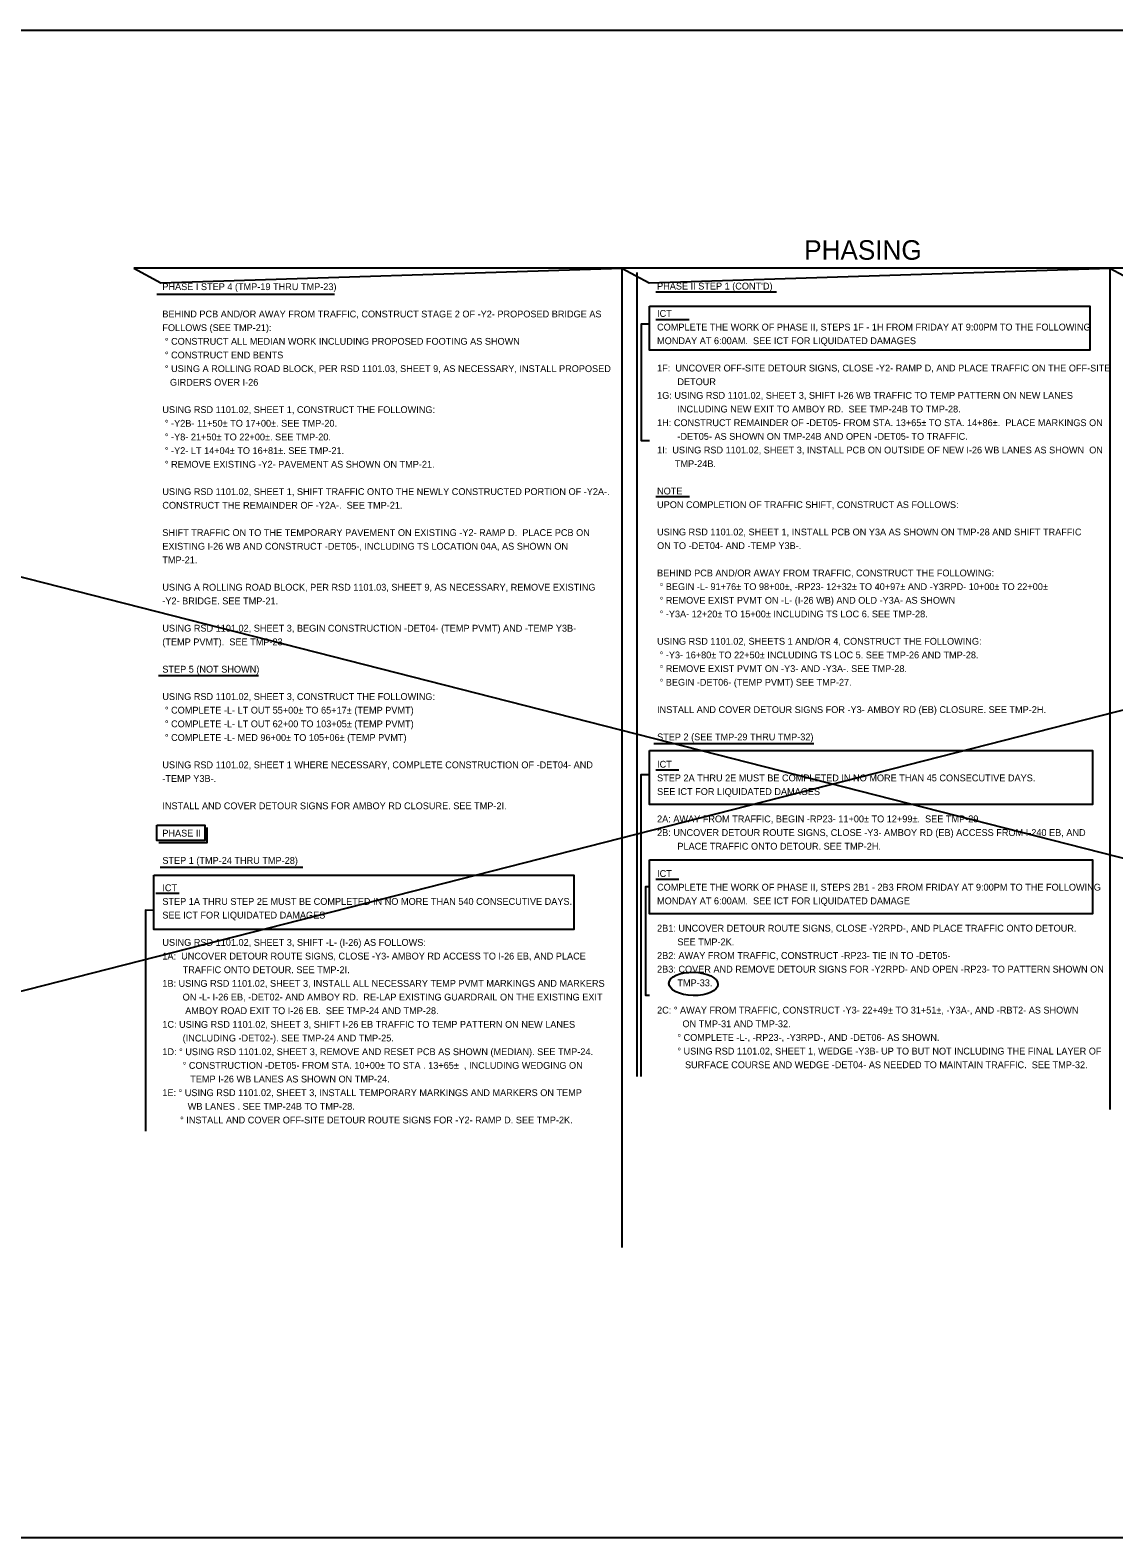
# Model space of a CAD drawing. Extents: x 2483905 to 2494512, y 366160 to 372330.
# Drawn here: x 2488905 to 2490016, y 368441 to 369986 of the extents above; entities that cross this region are included whole.
import ezdxf

# ---------------------------------------------------------------- set-up
doc = ezdxf.new("R2010")
doc.units = 0
for name, color, linetype in [('Scratch_Level_4', 7, 'Continuous'), ('Scratch_Level_6', 7, 'Continuous'), ('TC SHEET BORDER LINE THIN', 7, 'Continuous'), ('TC SHEET TEXT', 7, 'Continuous')]:
    doc.layers.add(name, color=color, linetype=linetype)

msp = doc.modelspace()

# ---------------------------------------------------------------- linework, layer by layer
at = {"layer": 'Scratch_Level_4'}
for p, q in [((2486701.2, 368441.1), (2492754.6, 369986.2)), ((2486701.2, 369986.2), (2492754.6, 368441.1))]:
    msp.add_line(p, q, dxfattribs=at)
msp.add_lwpolyline([(2486701.2, 369986.2), (2492754.6, 369986.2), (2492754.6, 368441.1), (2486701.2, 368441.1)], close=True, dxfattribs=at)
msp.add_ellipse((2489584.9, 369008.8), major_axis=(25.1, -0.5), ratio=0.476489, dxfattribs=at)
at = {"layer": 'Scratch_Level_6'}
msp.add_lwpolyline([(2489011.6, 369742.3), (2489039.5, 369727.3), (2489511.6, 369742.3), (2489539.5, 369727.3), (2490011.6, 369742.3), (2490039.5, 369727.3)], dxfattribs=at)
at = {"layer": 'TC SHEET BORDER LINE THIN'}
for p, q in [((2490511.6, 369742.3), (2489011.6, 369742.3)), ((2489511.6, 369742.3), (2489511.6, 368738.5)), ((2490011.6, 369742.3), (2490011.6, 368880.2)), ((2489035.4, 369715.6), (2489217.2, 369715.6)), ((2489546.4, 369718), (2489670.1, 369718)), ((2489546.4, 369689.8), (2489580.5, 369689.8)), ((2489546.4, 369508.2), (2489580.8, 369508.2)), ((2489036.9, 369324.9), (2489139.3, 369324.9)), ((2489544.5, 369255), (2489708.3, 369255)), ((2489546.4, 369228.2), (2489569.9, 369228.2)), ((2489038.6, 369128.3), (2489184.8, 369128.3)), ((2489546.4, 369116.2), (2489569.9, 369116.2)), ((2489034.4, 369101.9), (2489058, 369101.9))]:
    msp.add_line(p, q, dxfattribs=at)
for points in [[(2489526.8, 369738), (2489526.8, 368913.9)], [(2489540.1, 369685), (2489531.5, 369685), (2489531.5, 369565.6), (2489540.1, 369565.6)], [(2489540.1, 369223.1), (2489531.2, 369223.1), (2489531.2, 368913.9)], [(2489086.4, 369169.1), (2489086.4, 369153.4), (2489037.4, 369153.4)], [(2489540.1, 369108.3), (2489535.7, 369108.3), (2489535.7, 368997.4), (2489540.1, 368997.4)], [(2489031.5, 369084.1), (2489023.5, 369084.2), (2489023.5, 368857.8)]]:
    msp.add_lwpolyline(points, dxfattribs=at)
for points in [[(2489540.1, 369703.2), (2489990.9, 369703.2), (2489990.9, 369658.4), (2489540.1, 369658.4)], [(2489540.1, 369248.1), (2489993.8, 369248.1), (2489993.8, 369192.5), (2489540.1, 369192.5)], [(2489035.4, 369171.5), (2489084.4, 369171.5), (2489084.4, 369155.8), (2489035.4, 369155.8)], [(2489540.1, 369136.1), (2489993.8, 369136.1), (2489993.8, 369080.5), (2489540.1, 369080.5)], [(2489032.2, 369120.1), (2489462.4, 369120.1), (2489462.4, 369064.5), (2489032.2, 369064.5)]]:
    msp.add_lwpolyline(points, close=True, dxfattribs=at)

# ---------------------------------------------------------------- texts
for s, p in [('PHASE I STEP 4 (TMP-19 THRU TMP-23)', (2489040.9, 369719.8)), ("PHASE II STEP 1 (CONT'D)", (2489547.7, 369720.4)), ('BEHIND PCB AND/OR AWAY FROM TRAFFIC, CONSTRUCT STAGE 2 OF -Y2- PROPOSED BRIDGE AS', (2489040.9, 369691.8)), ('ICT', (2489547.7, 369692.4)), ('FOLLOWS (SEE TMP-21):', (2489040.9, 369677.8)), ('COMPLETE THE WORK OF PHASE II, STEPS 1F - 1H FROM FRIDAY AT 9:00PM TO THE FOLLOWING', (2489547.7, 369678.4)), (' ° CONSTRUCT ALL MEDIAN WORK INCLUDING PROPOSED FOOTING AS SHOWN', (2489040.9, 369663.8)), ('MONDAY AT 6:00AM.  SEE ICT FOR LIQUIDATED DAMAGES', (2489547.7, 369664.4)), (' ° CONSTRUCT END BENTS', (2489040.9, 369649.8)), (' ° USING A ROLLING ROAD BLOCK, PER RSD 1101.03, SHEET 9, AS NECESSARY, INSTALL PROPOSED ', (2489040.9, 369635.8)), ('1F:  UNCOVER OFF-SITE DETOUR SIGNS, CLOSE -Y2- RAMP D, AND PLACE TRAFFIC ON THE OFF-SITE ', (2489547.7, 369636.4)), ('   GIRDERS OVER I-26', (2489040.9, 369621.8)), ('        DETOUR', (2489547.7, 369622.4)), ('1G: USING RSD 1101.02, SHEET 3, SHIFT I-26 WB TRAFFIC TO TEMP PATTERN ON NEW LANES', (2489547.7, 369608.4)), ('USING RSD 1101.02, SHEET 1, CONSTRUCT THE FOLLOWING:', (2489040.9, 369593.8)), ('        INCLUDING NEW EXIT TO AMBOY RD.  SEE TMP-24B TO TMP-28.', (2489547.7, 369594.4)), (' ° -Y2B- 11+50± TO 17+00±. SEE TMP-20.', (2489040.9, 369579.8)), ('1H: CONSTRUCT REMAINDER OF -DET05- FROM STA. 13+65± TO STA. 14+86±.  PLACE MARKINGS ON ', (2489547.7, 369580.4)), (' ° -Y8- 21+50± TO 22+00±. SEE TMP-20.', (2489040.9, 369565.8)), ('        -DET05- AS SHOWN ON TMP-24B AND OPEN -DET05- TO TRAFFIC.', (2489547.7, 369566.4)), (' ° -Y2- LT 14+04± TO 16+81±. SEE TMP-21.', (2489040.9, 369551.8)), ('1I:  USING RSD 1101.02, SHEET 3, INSTALL PCB ON OUTSIDE OF NEW I-26 WB LANES AS SHOWN  ON ', (2489547.7, 369552.4)), (' ° REMOVE EXISTING -Y2- PAVEMENT AS SHOWN ON TMP-21.', (2489040.9, 369537.8)), ('       TMP-24B.', (2489547.7, 369538.4)), ('USING RSD 1101.02, SHEET 1, SHIFT TRAFFIC ONTO THE NEWLY CONSTRUCTED PORTION OF -Y2A-.', (2489040.9, 369509.8)), ('NOTE', (2489547.7, 369510.4)), ('CONSTRUCT THE REMAINDER OF -Y2A-.  SEE TMP-21.', (2489040.9, 369495.8)), ('UPON COMPLETION OF TRAFFIC SHIFT, CONSTRUCT AS FOLLOWS:', (2489547.7, 369496.4)), ('SHIFT TRAFFIC ON TO THE TEMPORARY PAVEMENT ON EXISTING -Y2- RAMP D.  PLACE PCB ON ', (2489040.9, 369467.8)), ('USING RSD 1101.02, SHEET 1, INSTALL PCB ON Y3A AS SHOWN ON TMP-28 AND SHIFT TRAFFIC', (2489547.7, 369468.4)), ('EXISTING I-26 WB AND CONSTRUCT -DET05-, INCLUDING TS LOCATION 04A, AS SHOWN ON', (2489040.9, 369453.8)), ('ON TO -DET04- AND -TEMP Y3B-.', (2489547.7, 369454.4)), ('TMP-21.', (2489040.9, 369439.8)), ('BEHIND PCB AND/OR AWAY FROM TRAFFIC, CONSTRUCT THE FOLLOWING:', (2489547.7, 369426.4)), ('USING A ROLLING ROAD BLOCK, PER RSD 1101.03, SHEET 9, AS NECESSARY, REMOVE EXISTING', (2489040.9, 369411.8)), (' ° BEGIN -L- 91+76± TO 98+00±, -RP23- 12+32± TO 40+97± AND -Y3RPD- 10+00± TO 22+00±', (2489547.7, 369412.4)), ('-Y2- BRIDGE. SEE TMP-21.', (2489040.9, 369397.8)), (' ° REMOVE EXIST PVMT ON -L- (I-26 WB) AND OLD -Y3A- AS SHOWN', (2489547.7, 369398.4)), (' ° -Y3A- 12+20± TO 15+00± INCLUDING TS LOC 6. SEE TMP-28.', (2489547.7, 369384.4)), ('USING RSD 1101.02, SHEET 3, BEGIN CONSTRUCTION -DET04- (TEMP PVMT) AND -TEMP Y3B-', (2489040.9, 369369.8)), ('(TEMP PVMT).  SEE TMP-23.', (2489040.9, 369355.8)), ('USING RSD 1101.02, SHEETS 1 AND/OR 4, CONSTRUCT THE FOLLOWING:', (2489547.7, 369356.4)), (' ° -Y3- 16+80± TO 22+50± INCLUDING TS LOC 5. SEE TMP-26 AND TMP-28.', (2489547.7, 369342.4)), ('STEP 5 (NOT SHOWN)', (2489040.9, 369327.8)), (' ° REMOVE EXIST PVMT ON -Y3- AND -Y3A-. SEE TMP-28.', (2489547.7, 369328.4)), (' ° BEGIN -DET06- (TEMP PVMT) SEE TMP-27.', (2489547.7, 369314.4)), ('USING RSD 1101.02, SHEET 3, CONSTRUCT THE FOLLOWING:', (2489040.9, 369299.8)), (' ° COMPLETE -L- LT OUT 55+00± TO 65+17± (TEMP PVMT)', (2489040.9, 369285.8)), ('INSTALL AND COVER DETOUR SIGNS FOR -Y3- AMBOY RD (EB) CLOSURE. SEE TMP-2H.', (2489547.7, 369286.4)), (' ° COMPLETE -L- LT OUT 62+00 TO 103+05± (TEMP PVMT)', (2489040.9, 369271.8)), (' ° COMPLETE -L- MED 96+00± TO 105+06± (TEMP PVMT)', (2489040.9, 369257.8)), ('STEP 2 (SEE TMP-29 THRU TMP-32)', (2489547.7, 369258.4)), ('USING RSD 1101.02, SHEET 1 WHERE NECESSARY, COMPLETE CONSTRUCTION OF -DET04- AND', (2489040.9, 369229.8)), ('ICT', (2489547.7, 369230.4)), ('-TEMP Y3B-.', (2489040.9, 369215.8)), ('STEP 2A THRU 2E MUST BE COMPLETED IN NO MORE THAN 45 CONSECUTIVE DAYS.', (2489547.7, 369216.4)), ('INSTALL AND COVER DETOUR SIGNS FOR AMBOY RD CLOSURE. SEE TMP-2I.', (2489040.9, 369187.8)), ('SEE ICT FOR LIQUIDATED DAMAGES', (2489547.7, 369202.4)), ('2A: AWAY FROM TRAFFIC, BEGIN -RP23- 11+00± TO 12+99±.  SEE TMP-29.', (2489547.7, 369174.4)), ('PHASE II', (2489040.9, 369159.8)), ('2B: UNCOVER DETOUR ROUTE SIGNS, CLOSE -Y3- AMBOY RD (EB) ACCESS FROM I-240 EB, AND', (2489547.7, 369160.4)), ('        PLACE TRAFFIC ONTO DETOUR. SEE TMP-2H.', (2489547.7, 369146.4)), ('STEP 1 (TMP-24 THRU TMP-28)', (2489040.9, 369131.8)), ('ICT', (2489547.7, 369118.4)), ('ICT', (2489040.9, 369103.8)), ('COMPLETE THE WORK OF PHASE II, STEPS 2B1 - 2B3 FROM FRIDAY AT 9:00PM TO THE FOLLOWING', (2489547.7, 369104.4)), ('STEP 1A THRU STEP 2E MUST BE COMPLETED IN NO MORE THAN 540 CONSECUTIVE DAYS.', (2489040.9, 369089.8)), ('MONDAY AT 6:00AM.  SEE ICT FOR LIQUIDATED DAMAGE', (2489547.7, 369090.4)), ('SEE ICT FOR LIQUIDATED DAMAGES', (2489040.9, 369075.8)), ('2B1: UNCOVER DETOUR ROUTE SIGNS, CLOSE -Y2RPD-, AND PLACE TRAFFIC ONTO DETOUR.', (2489547.7, 369062.4)), ('USING RSD 1101.02, SHEET 3, SHIFT -L- (I-26) AS FOLLOWS:', (2489040.9, 369047.8)), ('1A:  UNCOVER DETOUR ROUTE SIGNS, CLOSE -Y3- AMBOY RD ACCESS TO I-26 EB, AND PLACE', (2489040.9, 369033.8)), ('2B2: AWAY FROM TRAFFIC, CONSTRUCT -RP23- TIE IN TO -DET05-', (2489547.7, 369034.4)), ('        SEE TMP-2K.', (2489547.7, 369048.4)), ('        TRAFFIC ONTO DETOUR. SEE TMP-2I.', (2489040.9, 369019.8)), ('2B3: COVER AND REMOVE DETOUR SIGNS FOR -Y2RPD- AND OPEN -RP23- TO PATTERN SHOWN ON', (2489547.7, 369020.4)), ('1B: USING RSD 1101.02, SHEET 3, INSTALL ALL NECESSARY TEMP PVMT MARKINGS AND MARKERS', (2489040.9, 369005.8)), ('        TMP-33.', (2489547.7, 369006.4)), ('        ON -L- I-26 EB, -DET02- AND AMBOY RD.  RE-LAP EXISTING GUARDRAIL ON THE EXISTING EXIT', (2489040.9, 368991.8)), ('         AMBOY ROAD EXIT TO I-26 EB.  SEE TMP-24 AND TMP-28.', (2489040.9, 368977.8)), ('2C: ° AWAY FROM TRAFFIC, CONSTRUCT -Y3- 22+49± TO 31+51±, -Y3A-, AND -RBT2- AS SHOWN', (2489547.7, 368978.4)), ('1C: USING RSD 1101.02, SHEET 3, SHIFT I-26 EB TRAFFIC TO TEMP PATTERN ON NEW LANES', (2489040.9, 368963.8)), ('          ON TMP-31 AND TMP-32.', (2489547.7, 368964.4)), ('        (INCLUDING -DET02-). SEE TMP-24 AND TMP-25.', (2489040.9, 368949.8)), ('        ° COMPLETE -L-, -RP23-, -Y3RPD-, AND -DET06- AS SHOWN.', (2489547.7, 368950.4)), ('1D: ° USING RSD 1101.02, SHEET 3, REMOVE AND RESET PCB AS SHOWN (MEDIAN). SEE TMP-24.', (2489040.9, 368935.8)), ('        ° USING RSD 1101.02, SHEET 1, WEDGE -Y3B- UP TO BUT NOT INCLUDING THE FINAL LAYER OF', (2489547.7, 368936.4)), ('        ° CONSTRUCTION -DET05- FROM STA. 10+00± TO STA . 13+65±  , INCLUDING WEDGING ON ', (2489040.9, 368921.8)), ('           SURFACE COURSE AND WEDGE -DET04- AS NEEDED TO MAINTAIN TRAFFIC.  SEE TMP-32.', (2489547.7, 368922.4)), ('           TEMP I-26 WB LANES AS SHOWN ON TMP-24.', (2489040.9, 368907.8)), ('1E: ° USING RSD 1101.02, SHEET 3, INSTALL TEMPORARY MARKINGS AND MARKERS ON TEMP', (2489040.9, 368893.8)), ('          WB LANES . SEE TMP-24B TO TMP-28.', (2489040.9, 368879.8)), ('       ° INSTALL AND COVER OFF-SITE DETOUR ROUTE SIGNS FOR -Y2- RAMP D. SEE TMP-2K.', (2489040.9, 368865.8))]:
    msp.add_text(s, height=7, dxfattribs=at).set_placement(p)
at = {"layer": 'TC SHEET TEXT'}
msp.add_text('PHASING', height=20, rotation=359.9999, dxfattribs=at).set_placement((2489698.4, 369750.9))

doc.saveas('drawing.dxf')
